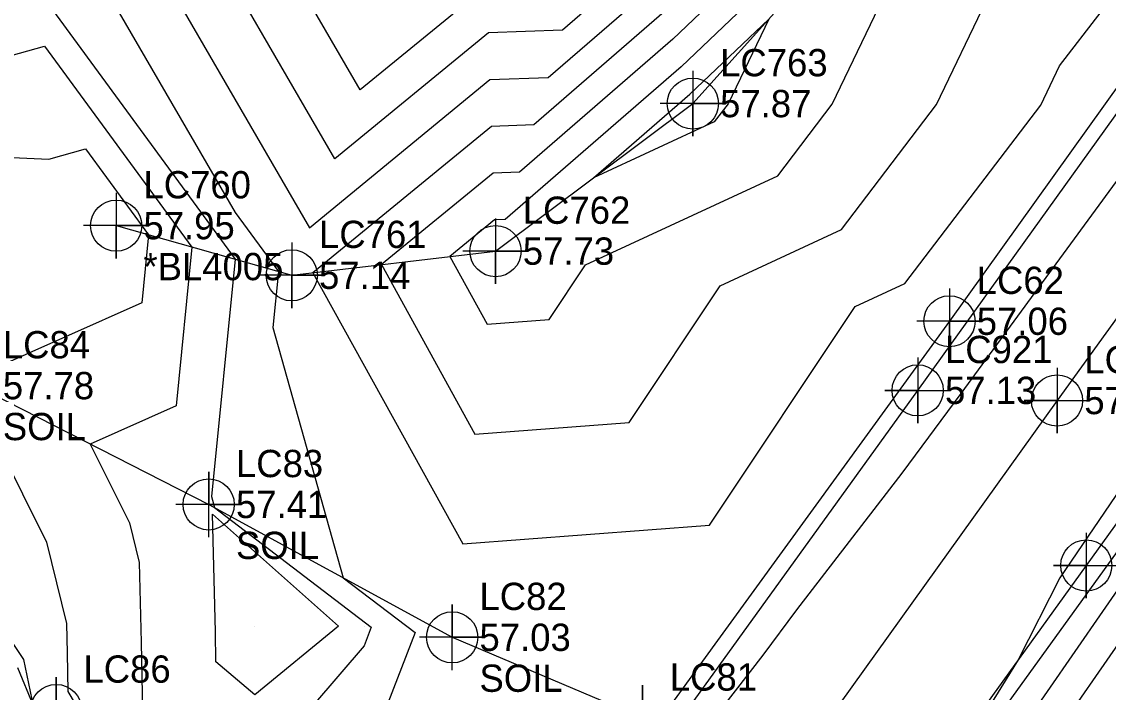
# Model space of a CAD drawing. Extents: x 2188792 to 2191981, y 386090 to 389710.
# Drawn here: x 2189598.9 to 2189698.4, y 386974.1 to 387035.5 of the extents above; entities that cross this region are included whole.
import ezdxf

# ---------------------------------------------------------------- set-up
doc = ezdxf.new("R2010")
doc.units = 0
for name, color, linetype in [('DTM Contours Major', 7, 'Continuous'), ('DTM Contours Minor', 7, 'Continuous'), ('Exist DTM Breakline', 7, 'Continuous'), ('Exist DTM Breakline Cogo Comment', 7, 'Continuous'), ('Exist DTM Breakline Cogo Elevation', 7, 'Continuous'), ('Exist DTM Breakline Cogo Number', 7, 'Continuous'), ('Exist DTM Breakline Cogo Point CELL', 7, 'Continuous'), ('Exist DTM QL2 LIDAR Elevation Point', 7, 'Continuous'), ('Exist Roads EOP', 7, 'Continuous'), ('Exist Roads EOP Cogo Elevation', 7, 'Continuous'), ('Exist Roads EOP Cogo Number', 7, 'Continuous'), ('Exist Roads EOP Cogo Point CELL', 7, 'Continuous'), ('Exist Roads EOT', 7, 'Continuous'), ('Exist Roads EOT Cogo Elevation', 7, 'Continuous'), ('Exist Roads EOT Cogo Number', 7, 'Continuous'), ('Exist Roads EOT Cogo Point CELL', 7, 'Continuous'), ('Exist Roads Soil Cogo Comment', 7, 'Continuous'), ('Exist Roads Soil Cogo Elevation', 7, 'Continuous'), ('Exist Roads Soil Cogo Number', 7, 'Continuous'), ('Exist Roads Soil Cogo Point CELL', 7, 'Continuous'), ('PH Exist DTM Breakline', 7, 'Continuous')]:
    doc.layers.add(name, color=color, linetype=linetype)

msp = doc.modelspace()

# ---------------------------------------------------------------- linework, layer by layer
at = {"layer": 'DTM Contours Major'}
for points in [[(2189608.657, 387045.199), (2189625.209, 387016.645), (2189641.764, 387030.215), (2189647.092, 387030.415), (2189656.933, 387038.945)], [(2189690.321, 386970.473), (2189702.993, 386988.788)], [(2189598.458, 386976.342), (2189599.911, 386972.861), (2189600.962, 386971.086), (2189600.085, 386967.099), (2189599.372, 386960.714), (2189598.635, 386960.347)]]:
    msp.add_lwpolyline(points, dxfattribs=at)
at = {"layer": 'DTM Contours Minor'}
for points in [[(2189657.721, 387036.426), (2189645.777, 387026.074), (2189641.902, 387025.928), (2189625.536, 387012.513), (2189639.26, 386987.658), (2189661.879, 386989.382), (2189675.22, 387009.407), (2189679.792, 387011.528), (2189692.235, 387027.881), (2189693.956, 387031.466), (2189709.218, 387051.316)], [(2189641.487, 387038.789), (2189629.873, 387029.269), (2189618.263, 387049.3)], [(2189656.145, 387041.464), (2189648.406, 387034.756), (2189641.625, 387034.502), (2189627.541, 387022.957), (2189613.46, 387047.249)], [(2189672.535, 387047.306), (2189658.509, 387033.907), (2189644.463, 387021.732), (2189642.041, 387021.642), (2189631.813, 387013.257), (2189640.389, 386997.723), (2189654.526, 386998.801), (2189662.864, 387011.316), (2189673.968, 387016.468), (2189682.683, 387027.922), (2189687.239, 387037.414)], [(2189675.423, 387046.792), (2189659.297, 387031.388), (2189643.148, 387017.391), (2189642.18, 387017.355), (2189638.089, 387014.002), (2189641.519, 387007.789), (2189647.173, 387008.22), (2189650.507, 387013.225), (2189668.144, 387021.408), (2189673.132, 387027.963), (2189680.522, 387043.362)], [(2189603.855, 387043.148), (2189618.418, 387018.024), (2189622.371, 387012.629), (2189621.861, 387007.494), (2189628.299, 386984.563), (2189634.896, 386979.534), (2189632.03, 386972.124)], [(2189601.657, 387036.604), (2189618.405, 387013.751), (2189616.243, 386991.995), (2189616.527, 386990.987), (2189630.888, 386980.036), (2189630.229, 386978.331), (2189623.177, 386970.118), (2189620.228, 386966.506), (2189616.533, 386963.306), (2189616.87, 386959.434), (2189615.516, 386952.703), (2189614.928, 386949.749), (2189614.132, 386943.507), (2189613.507, 386940.291), (2189606.553, 386934.556), (2189603.995, 386930.889), (2189600.424, 386925.77), (2189597.718, 386914.935)], [(2189660.086, 387028.869), (2189667.306, 387035.767), (2189663.58, 387028.004), (2189662.32, 387026.348), (2189651.251, 387021.212), (2189660.086, 387028.869)], [(2189593.055, 387031.078), (2189600.943, 387033.286), (2189614.438, 387014.872), (2189612.991, 387000.305), (2189605.127, 386996.816), (2189608.731, 386989.594), (2189609.618, 386985.949), (2189609.81, 386978.627), (2189609.937, 386970.781), (2189610.963, 386969.912), (2189609.922, 386969.011), (2189610.862, 386958.212), (2189610.327, 386955.551), (2189609.091, 386949.344), (2189608.729, 386946.512), (2189607.551, 386940.447), (2189604.061, 386937.568), (2189599.768, 386931.415), (2189593.775, 386922.823)], [(2189652.538, 386959.069), (2189666.8, 386977.462), (2189669.874, 386981.626), (2189679.548, 386994.139), (2189684.935, 387001.445), (2189696.907, 387017.785), (2189701.439, 387023.972)], [(2189597.988, 387023.09), (2189601.324, 387022.926), (2189604.699, 387023.87), (2189610.471, 387015.993), (2189609.852, 387009.762), (2189595.824, 387003.54)], [(2189707.688, 387004.715), (2189696.068, 386987.603), (2189693.972, 386984.568), (2189690.18, 386977.049), (2189683.33, 386965.967)], [(2189594.519, 387001.065), (2189601.128, 386987.823), (2189602.944, 386980.358), (2189603.015, 386977.654), (2189603.072, 386974.14), (2189605.269, 386970.427), (2189604.037, 386964.824), (2189604.651, 386958.391), (2189601.761, 386953.606), (2189601.732, 386949.645), (2189601.666, 386940.969), (2189601.595, 386940.603), (2189601.568, 386940.581), (2189601.488, 386940.465), (2189601.205, 386940.706), (2189595.646, 386945.562)], [(2189616.322, 386990.396), (2189627.871, 386980.119), (2189620.228, 386973.839), (2189616.649, 386976.871), (2189616.604, 386979.6), (2189616.322, 386990.396)], [(2189694.937, 386972.126), (2189701.702, 386981.904)]]:
    msp.add_lwpolyline(points, dxfattribs=at)
at = {"layer": 'Exist DTM Breakline'}
for points in [[(2189607.506, 387016.831), (2189623.597, 387012.283), (2189642.272, 387014.498), (2189660.352, 387028.018), (2189676.956, 387046.52), (2189681.742, 387066.606), (2189693.435, 387091.443), (2189694.547, 387115.301), (2189671.434, 387126.078)], [(2189594.621, 387002.171), (2189615.985, 386991.282), (2189638.3, 386979.107), (2189655.743, 386971.72)]]:
    msp.add_lwpolyline(points, dxfattribs=at)
at = {"layer": 'Exist DTM Breakline Cogo Point CELL'}
for points in [[(2189660.352, 387031.018), (2189660.352, 387025.018), (2189660.352, 387028.018), (2189663.352, 387028.018), (2189657.352, 387028.018)], [(2189607.506, 387019.831), (2189607.506, 387013.831), (2189607.506, 387016.831), (2189610.506, 387016.831), (2189604.506, 387016.831)], [(2189642.272, 387017.498), (2189642.272, 387011.498), (2189642.272, 387014.498), (2189645.272, 387014.498), (2189639.272, 387014.498)], [(2189623.597, 387015.283), (2189623.597, 387009.283), (2189623.597, 387012.283), (2189626.597, 387012.283), (2189620.597, 387012.283)]]:
    msp.add_lwpolyline(points, dxfattribs=at)
for centre in [(2189660.352, 387028.018), (2189607.506, 387016.831), (2189642.272, 387014.498), (2189623.597, 387012.283)]:
    msp.add_circle(centre, 2.344, dxfattribs=at)
at = {"layer": 'Exist DTM QL2 LIDAR Elevation Point'}
for p, q in [((2189620.228, 386980.119), (2189620.228, 386980.119)), ((2189630.229, 386980.119), (2189630.229, 386980.119))]:
    msp.add_line(p, q, dxfattribs=at)
at = {"layer": 'Exist Roads EOP'}
for points in [[(2190313.986, 387884.141), (2190285.547, 387843.636), (2190254.588, 387800.045), (2190225.155, 387759.32), (2190194.829, 387717.425), (2190164.291, 387675.101), (2190137.229, 387637.301), (2190105.098, 387592.774), (2190071.411, 387546.221), (2190039.296, 387501.568), (2190007.542, 387457.958), (2189976.844, 387415.407), (2189936.359, 387359.145), (2189907.138, 387318.716), (2189868.636, 387265.243), (2189836.428, 387220.463), (2189805.695, 387177.815), (2189775.592, 387135.957), (2189745.498, 387094.055), (2189715.496, 387052.249), (2189683.869, 387008.07), (2189653.218, 386965.867), (2189623.729, 386924.667)], [(2190335.128, 387868.989), (2190306.373, 387829.271), (2190274.581, 387784.921), (2190245.133, 387744.071), (2190214.553, 387701.741), (2190184.89, 387660.475), (2190157.493, 387622.204), (2190126.048, 387578.501), (2190091.216, 387530.568), (2190059.634, 387486.726), (2190026.932, 387441.783), (2189997.689, 387401.032), (2189957.023, 387344.154), (2189927.908, 387303.922), (2189889.008, 387250.224), (2189856.606, 387205.5), (2189825.68, 387162.612), (2189795.668, 387120.822), (2189765.955, 387079.619), (2189734.998, 387036.704), (2189703.849, 386993.356), (2189673.984, 386951.979), (2189643.253, 386909.427)]]:
    msp.add_lwpolyline(points, dxfattribs=at)
at = {"layer": 'Exist Roads EOP Cogo Point CELL'}
msp.add_lwpolyline([(2189683.869, 387011.07), (2189683.869, 387005.07), (2189683.869, 387008.07), (2189686.869, 387008.07), (2189680.869, 387008.07)], dxfattribs=at)
msp.add_circle((2189683.869, 387008.07), 2.344, dxfattribs=at)
at = {"layer": 'Exist Roads EOT'}
for points in [[(2190174.375, 387667.889), (2190147.471, 387630.495), (2190115.247, 387585.778), (2190081.202, 387538.232), (2190049.502, 387494.256), (2190017.538, 387450.182), (2189987.334, 387408.357), (2189946.666, 387352.019), (2189917.402, 387311.129), (2189878.955, 387257.772), (2189846.565, 387212.819), (2189815.837, 387170.306), (2189785.374, 387128.351), (2189755.717, 387086.921), (2189724.953, 387044.041), (2189693.727, 387000.805), (2189663.933, 386959.217), (2189633.425, 386917.196)], [(2189989.253, 387391.986), (2189958.581, 387349.453), (2189928.09, 387307.216), (2189909.67, 387281.603), (2189884.44, 387246.513), (2189852.91, 387202.766), (2189821.507, 387159.305), (2189790.01, 387115.85), (2189759.16, 387072.957), (2189728.247, 387029.91), (2189696.407, 386985.689), (2189665.45, 386942.736), (2189635.049, 386900.502)], [(2189619.904, 386917.168), (2189650.19, 386959.038), (2189680.959, 387001.734), (2189713.171, 387046.57), (2189739.87, 387083.883), (2189771.556, 387127.847), (2189803.188, 387171.311), (2189835.065, 387215.496), (2189866.485, 387259.202), (2189892.308, 387295.019), (2189910.407, 387320.236), (2189942.075, 387364.22)]]:
    msp.add_lwpolyline(points, dxfattribs=at)
at = {"layer": 'Exist Roads EOT Cogo Point CELL'}
for points in [[(2189680.959, 387004.734), (2189680.959, 386998.734), (2189680.959, 387001.734), (2189677.959, 387001.734), (2189683.959, 387001.734)], [(2189693.727, 387003.805), (2189693.727, 386997.805), (2189693.727, 387000.805), (2189690.727, 387000.805), (2189696.727, 387000.805)], [(2189696.407, 386988.689), (2189696.407, 386982.689), (2189696.407, 386985.689), (2189693.407, 386985.689), (2189699.407, 386985.689)]]:
    msp.add_lwpolyline(points, dxfattribs=at)
for centre in [(2189680.959, 387001.734), (2189693.727, 387000.805), (2189696.407, 386985.689)]:
    msp.add_circle(centre, 2.344, dxfattribs=at)
at = {"layer": 'Exist Roads Soil Cogo Point CELL'}
for points in [[(2189615.985, 386988.282), (2189615.985, 386994.282), (2189615.985, 386991.282), (2189618.985, 386991.282), (2189612.985, 386991.282)], [(2189638.3, 386976.107), (2189638.3, 386982.107), (2189638.3, 386979.107), (2189641.3, 386979.107), (2189635.3, 386979.107)], [(2189602.01, 386969.445), (2189602.01, 386975.445), (2189602.01, 386972.445), (2189605.01, 386972.445), (2189599.01, 386972.445)], [(2189655.743, 386968.72), (2189655.743, 386974.72), (2189655.743, 386971.72), (2189658.743, 386971.72), (2189652.743, 386971.72)]]:
    msp.add_lwpolyline(points, dxfattribs=at)
for centre in [(2189615.985, 386991.282), (2189638.3, 386979.107), (2189602.01, 386972.445)]:
    msp.add_circle(centre, 2.344, dxfattribs=at)
at = {"layer": 'PH Exist DTM Breakline'}
msp.add_lwpolyline([(2189597.749, 386950.654), (2189599.806, 386960.464), (2189600.257, 386971.193), (2189599.036, 386977.084), (2189593.131, 386985.961)], dxfattribs=at)

# ---------------------------------------------------------------- texts
at = {"layer": 'Exist DTM Breakline Cogo Comment'}
msp.add_text('*BL4005', height=2.5, dxfattribs=at).set_placement((2189610.006, 387011.831))
at = {"layer": 'Exist DTM Breakline Cogo Elevation'}
for s, p in [('57.87', (2189662.852, 387026.768)), ('57.95', (2189610.006, 387015.581)), ('57.73', (2189644.772, 387013.248)), ('57.14', (2189626.097, 387011.033))]:
    msp.add_text(s, height=2.5, dxfattribs=at).set_placement(p)
at = {"layer": 'Exist DTM Breakline Cogo Number'}
for s, p in [('LC763', (2189662.852, 387030.518)), ('LC760', (2189610.006, 387019.331)), ('LC762', (2189644.772, 387016.998)), ('LC761', (2189626.097, 387014.783))]:
    msp.add_text(s, height=2.5, dxfattribs=at).set_placement(p)
at = {"layer": 'Exist Roads EOP Cogo Elevation'}
msp.add_text('57.06', height=2.5, dxfattribs=at).set_placement((2189686.369, 387006.82))
at = {"layer": 'Exist Roads EOP Cogo Number'}
msp.add_text('LC62', height=2.5, dxfattribs=at).set_placement((2189686.369, 387010.57))
at = {"layer": 'Exist Roads EOT Cogo Elevation'}
for s, p in [('57.13', (2189683.459, 387000.484)), ('57.35', (2189696.227, 386999.555))]:
    msp.add_text(s, height=2.5, dxfattribs=at).set_placement(p)
at = {"layer": 'Exist Roads EOT Cogo Number'}
for s, p in [('LC921', (2189683.459, 387004.234)), ('LC61', (2189696.227, 387003.305))]:
    msp.add_text(s, height=2.5, dxfattribs=at).set_placement(p)
at = {"layer": 'Exist Roads Soil Cogo Comment'}
for p in [(2189597.121, 386997.171), (2189618.485, 386986.282), (2189640.8, 386974.107)]:
    msp.add_text('SOIL', height=2.5, dxfattribs=at).set_placement(p)
at = {"layer": 'Exist Roads Soil Cogo Elevation'}
for s, p in [('57.78', (2189597.121, 387000.921)), ('57.41', (2189618.485, 386990.032)), ('57.03', (2189640.8, 386977.857))]:
    msp.add_text(s, height=2.5, dxfattribs=at).set_placement(p)
at = {"layer": 'Exist Roads Soil Cogo Number'}
for s, p in [('LC84', (2189597.121, 387004.671)), ('LC83', (2189618.485, 386993.782)), ('LC82', (2189640.8, 386981.607)), ('LC86', (2189604.51, 386974.945)), ('LC81', (2189658.243, 386974.22))]:
    msp.add_text(s, height=2.5, dxfattribs=at).set_placement(p)

doc.saveas('drawing.dxf')
